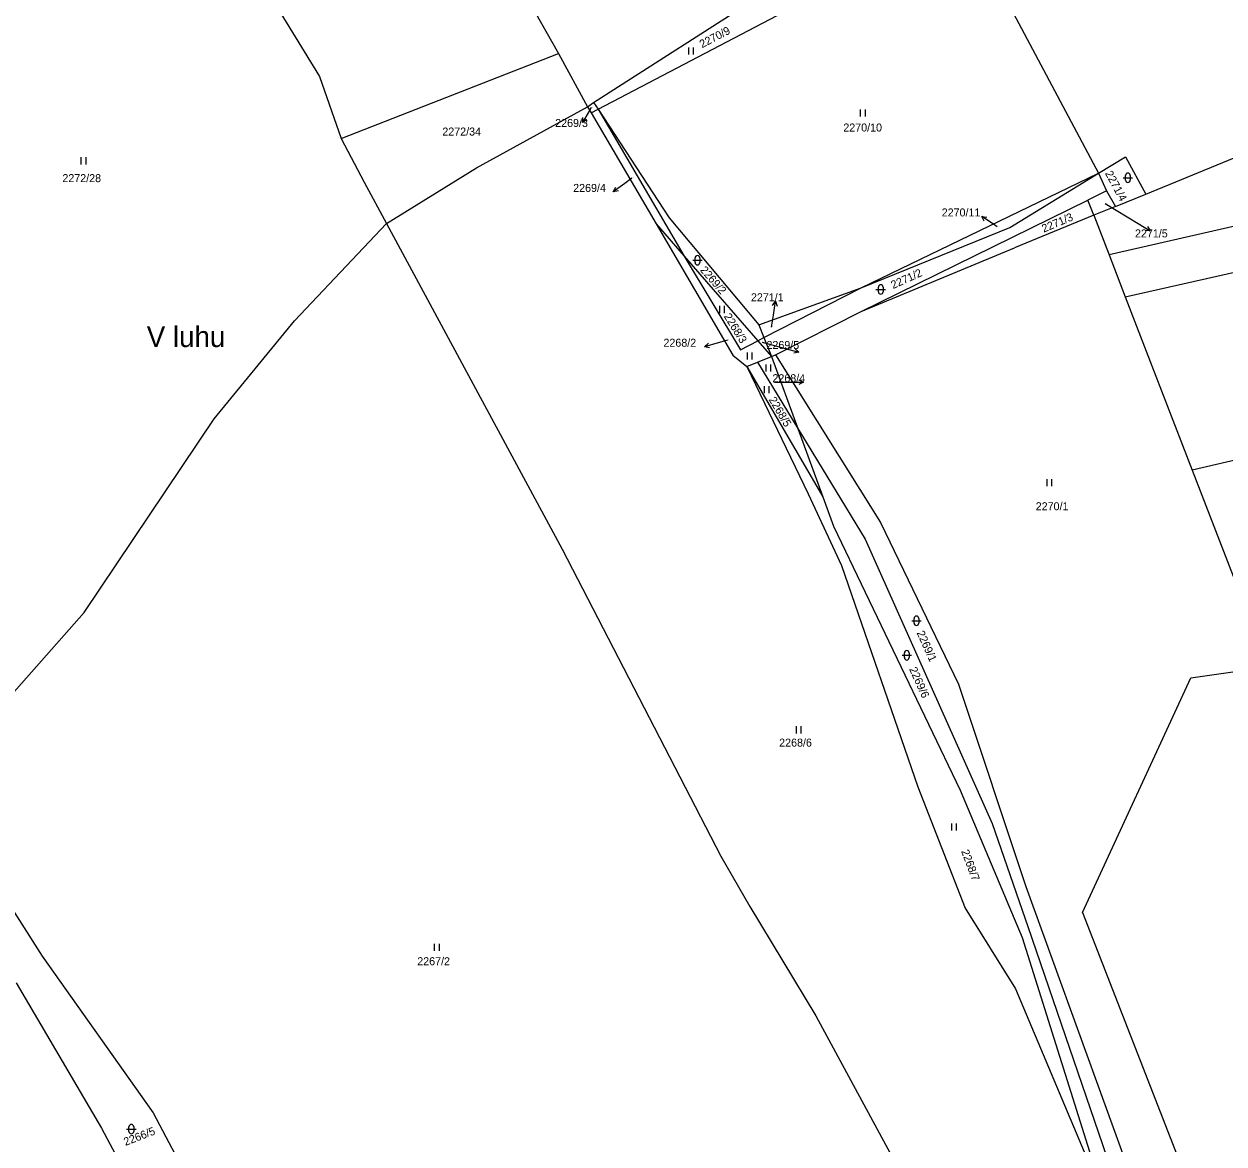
# Model space of a CAD drawing. Extents: x -785744 to -782822, y -1067550 to -1063910.
# Drawn here: x -784357.2 to -784102.3, y -1066179.1 to -1065941.1 of the extents above; entities that cross this region are included whole.
import ezdxf

# ---------------------------------------------------------------- set-up
doc = ezdxf.new("R2010")
doc.units = 0
for name, color, linetype in [('Hranice parcel', 7, 'Continuous'), ('Parcelní čísla', 7, 'Continuous'), ('Pop_ČP_popisy', 7, 'Continuous'), ('Značky kultur', 7, 'Continuous')]:
    doc.layers.add(name, color=color, linetype=linetype)

msp = doc.modelspace()

# ---------------------------------------------------------------- linework, layer by layer
at = {"layer": 'Hranice parcel'}
for p, q in [((-784069.5, -1065977.09), (-784126.7, -1065990.16)), ((-784129.94, -1065981.76), (-784126.7, -1065990.16)), ((-784123.25, -1065999.11), (-784079.15, -1065989.04)), ((-784126.7, -1065990.16), (-784123.25, -1065999.11)), ((-784123.25, -1065999.11), (-784109.07, -1066035.88)), ((-784060.8, -1066024.85), (-784109.07, -1066035.88)), ((-784109.07, -1066035.88), (-784095.4, -1066071.3))]:
    msp.add_line(p, q, dxfattribs=at)
for points in [[(-784262.9, -1065913.45), (-784243.67, -1065947.37)], [(-784236.21, -1065957.81), (-784199.46, -1065934.17)], [(-784303.46, -1065937.58), (-784294.45, -1065952.24)], [(-784148.24, -1065936.63), (-784128.96, -1065972.83)], [(-784235.28, -1065959.23), (-784197.2, -1065939.28)], [(-784289.83, -1065965.43), (-784243.67, -1065947.37)], [(-784243.67, -1065947.37), (-784237.51, -1065958.69)], [(-784294.45, -1065952.24), (-784289.83, -1065965.43)], [(-784261.13, -1065971.67), (-784237.51, -1065958.69)], [(-784237.51, -1065958.69), (-784236.21, -1065957.81)], [(-784237.51, -1065958.69), (-784236.74, -1065960)], [(-784236.21, -1065957.81), (-784235.28, -1065959.23)], [(-784236.74, -1065960), (-784235.28, -1065959.23)], [(-784236.74, -1065960), (-784222.93, -1065983.6)], [(-784235.28, -1065959.23), (-784220.17, -1065982.32)], [(-784235.28, -1065959.23), (-784217.01, -1065990.41)], [(-784118.91, -1065977.24), (-784076.2, -1065959.73)], [(-784289.83, -1065965.43), (-784284.94, -1065974.72)], [(-784280.23, -1065983.53), (-784261.13, -1065971.67)], [(-784128.96, -1065972.83), (-784123.24, -1065969.33)], [(-784123.24, -1065969.33), (-784118.91, -1065977.24)], [(-784179.39, -1065997.15), (-784128.96, -1065972.83)], [(-784147.76, -1065984.34), (-784128.96, -1065972.83)], [(-784128.96, -1065972.83), (-784127.21, -1065976.56)], [(-784284.94, -1065974.72), (-784280.23, -1065983.53)], [(-784127.21, -1065976.56), (-784131.19, -1065978.52)], [(-784127.21, -1065976.56), (-784125.35, -1065979.88)], [(-784179.4, -1066002.21), (-784131.19, -1065978.52)], [(-784129.94, -1065981.76), (-784131.19, -1065978.52)], [(-784125.35, -1065979.88), (-784118.91, -1065977.24)], [(-784129.94, -1065981.76), (-784146.8, -1065988.69)], [(-784125.35, -1065979.88), (-784129.94, -1065981.76)], [(-784299.79, -1066004.21), (-784280.23, -1065983.53)], [(-784280.23, -1065983.53), (-784242.91, -1066052.7)], [(-784222.93, -1065983.6), (-784217.01, -1065990.41)], [(-784222.93, -1065983.6), (-784206.64, -1066011.48)], [(-784220.17, -1065982.32), (-784201.1, -1066005.05)], [(-784179.39, -1065997.15), (-784147.76, -1065984.34)], [(-784179.4, -1066002.21), (-784146.8, -1065988.69)], [(-784217.01, -1065990.41), (-784201.35, -1066008.43)], [(-784217.01, -1065990.41), (-784205.01, -1066010.31)], [(-784201.1, -1066005.05), (-784179.39, -1065997.15)], [(-784200.03, -1066007.75), (-784179.39, -1065997.15)], [(-784197.56, -1066011.42), (-784179.4, -1066002.21)], [(-784316.82, -1066025), (-784299.79, -1066004.21)], [(-784201.1, -1066005.05), (-784200.03, -1066007.75)], [(-784205.01, -1066010.31), (-784201.35, -1066008.43)], [(-784201.35, -1066008.43), (-784200.03, -1066007.75)], [(-784201.35, -1066008.43), (-784198.45, -1066011.76)], [(-784200.03, -1066007.75), (-784198.45, -1066011.76)], [(-784206.64, -1066011.48), (-784203.66, -1066013.87)], [(-784201.43, -1066012.97), (-784198.45, -1066011.76)], [(-784198.45, -1066011.76), (-784197.56, -1066011.42)], [(-784198.45, -1066011.76), (-784192.84, -1066027.05)], [(-784197.56, -1066011.42), (-784175.24, -1066047.02)], [(-784203.66, -1066013.87), (-784201.43, -1066012.97)], [(-784203.66, -1066013.87), (-784187.52, -1066041.56)], [(-784203.66, -1066013.87), (-784190.63, -1066040.95)], [(-784201.43, -1066012.97), (-784192.84, -1066027.05)], [(-784344.45, -1066066.14), (-784316.82, -1066025)], [(-784192.84, -1066027.05), (-784187.52, -1066041.56)], [(-784192.84, -1066027.05), (-784178.49, -1066050.54)], [(-784190.63, -1066040.95), (-784183.58, -1066056.13)], [(-784187.52, -1066041.56), (-784185.22, -1066047.82)], [(-784185.22, -1066047.82), (-784158.34, -1066103.92)], [(-784175.24, -1066047.02), (-784158.66, -1066081.36)], [(-784178.49, -1066050.54), (-784151.54, -1066110.99)], [(-784242.91, -1066052.7), (-784209.2, -1066117.92)], [(-784183.58, -1066056.13), (-784167.32, -1066103.21)], [(-784380.24, -1066106.55), (-784344.45, -1066066.14)], [(-784109.33, -1066080.04), (-784092.94, -1066077.69)], [(-784132.35, -1066129.85), (-784109.33, -1066080.04)], [(-784158.66, -1066081.36), (-784144.36, -1066124.36)], [(-784167.32, -1066103.21), (-784157.3, -1066128.96)], [(-784158.34, -1066103.92), (-784145.14, -1066135.22)], [(-784151.54, -1066110.99), (-784143.98, -1066132.84)], [(-784209.2, -1066117.92), (-784203.02, -1066128.62)], [(-784363.61, -1066123.2), (-784353.39, -1066139.17)], [(-784144.36, -1066124.36), (-784121.99, -1066186.11)], [(-784203.02, -1066128.62), (-784189.02, -1066151.85)], [(-784157.3, -1066128.96), (-784146.56, -1066146.11)], [(-784132.35, -1066129.85), (-784111.61, -1066183.16)], [(-784143.98, -1066132.84), (-784125.39, -1066187.07)], [(-784145.14, -1066135.22), (-784130.05, -1066183.12)], [(-784353.39, -1066139.17), (-784329.83, -1066172.47)], [(-784358.9, -1066144.83), (-784340.76, -1066175.73)], [(-784146.56, -1066146.11), (-784130.87, -1066183.45)], [(-784189.02, -1066151.85), (-784165.74, -1066194.77)], [(-784329.83, -1066172.47), (-784318.48, -1066193.88)], [(-784340.76, -1066175.73), (-784327.32, -1066201.01)]]:
    msp.add_lwpolyline(points, dxfattribs=at)
at = {"layer": 'Pop_ČP_popisy'}
for p, q in [((-784237.09, -1065959.47), (-784238.58, -1065962.07)), ((-784229.62, -1065975), (-784232.03, -1065976.79)), ((-784151.27, -1065983.67), (-784153.76, -1065982)), ((-784120.52, -1065983.5), (-784117.95, -1065985.05)), ((-784198.01, -1066002.98), (-784197.55, -1066000.02)), ((-784209.78, -1066008.87), (-784212.67, -1066009.68)), ((-784195.5, -1066010.03), (-784192.61, -1066010.82)), ((-784194.64, -1066017.22), (-784191.64, -1066017.22))]:
    msp.add_line(p, q, dxfattribs=at)
for points in [[(-784236.75, -1065958.87), (-784237.09, -1065959.47)], [(-784237.65, -1065961.45), (-784238.58, -1065962.07), (-784238.52, -1065960.96)], [(-784228.07, -1065973.85), (-784229.62, -1065975)], [(-784230.93, -1065976.59), (-784232.03, -1065976.79), (-784231.52, -1065975.79)], [(-784127.52, -1065979.28), (-784120.52, -1065983.5)], [(-784153.21, -1065982.97), (-784153.76, -1065982), (-784152.65, -1065982.14)], [(-784150.5, -1065984.18), (-784151.27, -1065983.67)], [(-784118.55, -1065984.1), (-784117.95, -1065985.05), (-784119.06, -1065984.96)], [(-784198.19, -1066000.93), (-784197.55, -1066000.02), (-784197.21, -1066001.08)], [(-784198.41, -1066005.51), (-784198.01, -1066002.98)], [(-784211.57, -1066009.89), (-784212.67, -1066009.68), (-784211.84, -1066008.93)], [(-784207.74, -1066008.3), (-784209.78, -1066008.87)], [(-784200.43, -1066008.69), (-784195.5, -1066010.03)], [(-784193.44, -1066010.07), (-784192.61, -1066010.82), (-784193.7, -1066011.04)], [(-784197.79, -1066017.22), (-784194.64, -1066017.22)], [(-784192.64, -1066016.72), (-784191.64, -1066017.22), (-784192.64, -1066017.72)]]:
    msp.add_lwpolyline(points, dxfattribs=at)
at = {"layer": 'Značky kultur'}
for p, q in [((-784215.98, -1065947.61), (-784215.98, -1065946.11)), ((-784214.98, -1065947.61), (-784214.98, -1065946.11)), ((-784179.48, -1065960.74), (-784179.48, -1065959.24)), ((-784178.48, -1065960.74), (-784178.48, -1065959.24)), ((-784345.07, -1065970.93), (-784345.07, -1065969.43)), ((-784344.07, -1065970.93), (-784344.07, -1065969.43)), ((-784123.7, -1065973.77), (-784121.7, -1065973.77)), ((-784123.2, -1065974.27), (-784123.2, -1065973.27)), ((-784122.2, -1065973.27), (-784122.2, -1065974.27)), ((-784215.15, -1065991.31), (-784213.15, -1065991.31)), ((-784214.65, -1065991.81), (-784214.65, -1065990.81)), ((-784213.65, -1065990.81), (-784213.65, -1065991.81)), ((-784175.72, -1065998.01), (-784175.72, -1065997.01)), ((-784174.72, -1065997.01), (-784174.72, -1065998.01)), ((-784176.22, -1065997.51), (-784174.22, -1065997.51)), ((-784209.41, -1066002.52), (-784209.41, -1066001.02)), ((-784208.41, -1066002.52), (-784208.41, -1066001.02)), ((-784203.52, -1066012.37), (-784203.52, -1066010.87)), ((-784202.52, -1066012.37), (-784202.52, -1066010.87)), ((-784199.58, -1066014.97), (-784199.58, -1066013.47)), ((-784198.58, -1066014.97), (-784198.58, -1066013.47)), ((-784199.91, -1066019.55), (-784199.91, -1066018.05)), ((-784198.91, -1066019.55), (-784198.91, -1066018.05)), ((-784139.84, -1066039.33), (-784139.84, -1066037.83)), ((-784138.84, -1066039.33), (-784138.84, -1066037.83)), ((-784168.63, -1066067.89), (-784166.63, -1066067.89)), ((-784168.13, -1066068.39), (-784168.13, -1066067.39)), ((-784167.13, -1066067.39), (-784167.13, -1066068.39)), ((-784170.68, -1066075.24), (-784168.68, -1066075.24)), ((-784170.18, -1066075.74), (-784170.18, -1066074.74)), ((-784169.18, -1066074.74), (-784169.18, -1066075.74)), ((-784193.1, -1066091.82), (-784193.1, -1066090.32)), ((-784192.1, -1066091.82), (-784192.1, -1066090.32)), ((-784160.12, -1066112.48), (-784160.12, -1066110.98)), ((-784159.12, -1066112.48), (-784159.12, -1066110.98)), ((-784269.99, -1066138.01), (-784269.99, -1066136.51)), ((-784268.99, -1066138.01), (-784268.99, -1066136.51)), ((-784334.94, -1066176.41), (-784334.94, -1066175.41)), ((-784333.94, -1066175.41), (-784333.94, -1066176.41)), ((-784335.44, -1066175.91), (-784333.44, -1066175.91))]:
    msp.add_line(p, q, dxfattribs=at)
for centre, start, end in [((-784122.7, -1065973.27), 0, 180), ((-784122.7, -1065974.27), 180, 0), ((-784214.15, -1065990.81), 0, 180), ((-784214.15, -1065991.81), 180, 0), ((-784175.22, -1065997.01), 0, 180), ((-784175.22, -1065998.01), 180, 0), ((-784167.63, -1066067.39), 0, 180), ((-784167.63, -1066068.39), 180, 0), ((-784169.68, -1066074.74), 0, 180), ((-784169.68, -1066075.74), 180, 0), ((-784334.44, -1066175.41), 0, 180), ((-784334.44, -1066176.41), 180, 0)]:
    msp.add_arc(centre, 0.5, start, end, dxfattribs=at)

# ---------------------------------------------------------------- texts
at = {"layer": 'Parcelní čísla'}
for s, rotation, p in [('2270/9', 27.5863, (-784213.17, -1065946.26)), ('2271/4', 298.2749, (-784127.6, -1065972.84)), ('2271/3', 22.9717, (-784140.57, -1065985.45)), ('2269/2', 311.0353, (-784213.7, -1065993.46)), ('2271/2', 24.3294, (-784172.59, -1065997.44)), ('2268/3', 301.8025, (-784208.62, -1066003.22)), ('2268/5', 300.4962, (-784199.07, -1066020.91)), ('2269/1', 294.1758, (-784167.61, -1066070.46)), ('2269/6', 294.2277, (-784169.21, -1066078.17)), ('2268/7', 290.7654, (-784158.16, -1066116.86)), ('2266/5', 21.1586, (-784335.68, -1066179.48))]:
    msp.add_text(s, height=1.7, rotation=rotation, dxfattribs=at).set_placement(p)
for s, height, p in [('2269/3', 0.1, (-784236.75, -1065958.87)), ('2272/34', 1.7, (-784268.36, -1065964.81)), ('2270/10', 1.7, (-784183.16, -1065963.95)), ('2272/28', 1.7, (-784349.09, -1065974.71)), ('2269/4', 0.1, (-784228.07, -1065973.85)), ('2271/5', 0.1, (-784127.52, -1065979.28)), ('2270/11', 0.1, (-784150.5, -1065984.18)), ('2271/1', 0.1, (-784198.41, -1066005.51)), ('2268/2', 0.1, (-784207.74, -1066008.3)), ('2269/5', 0.1, (-784200.43, -1066008.69)), ('2268/4', 0.1, (-784197.79, -1066017.22)), ('2270/1', 1.7, (-784142.28, -1066044.42)), ('2268/6', 1.7, (-784196.79, -1066094.64)), ('2267/2', 1.7, (-784273.69, -1066141.09))]:
    msp.add_text(s, height=height, dxfattribs=at).set_placement(p)
at = {"layer": 'Pop_ČP_popisy'}
for s, height, p in [('2269/3', 1.7, (-784244.38, -1065962.99)), ('2269/4', 1.7, (-784240.56, -1065976.79)), ('2270/11', 1.7, (-784162.26, -1065982)), ('2271/5', 1.7, (-784121.19, -1065986.45)), ('2271/1', 1.7, (-784202.79, -1066000.02)), ('V luhu', 4.4, (-784331.16, -1066009.74)), ('2268/2', 1.7, (-784221.38, -1066009.68)), ('2269/5', 1.7, (-784199.49, -1066010.16)), ('2268/4', 1.7, (-784198.22, -1066017.22))]:
    msp.add_text(s, height=height, dxfattribs=at).set_placement(p)

doc.saveas('drawing.dxf')
